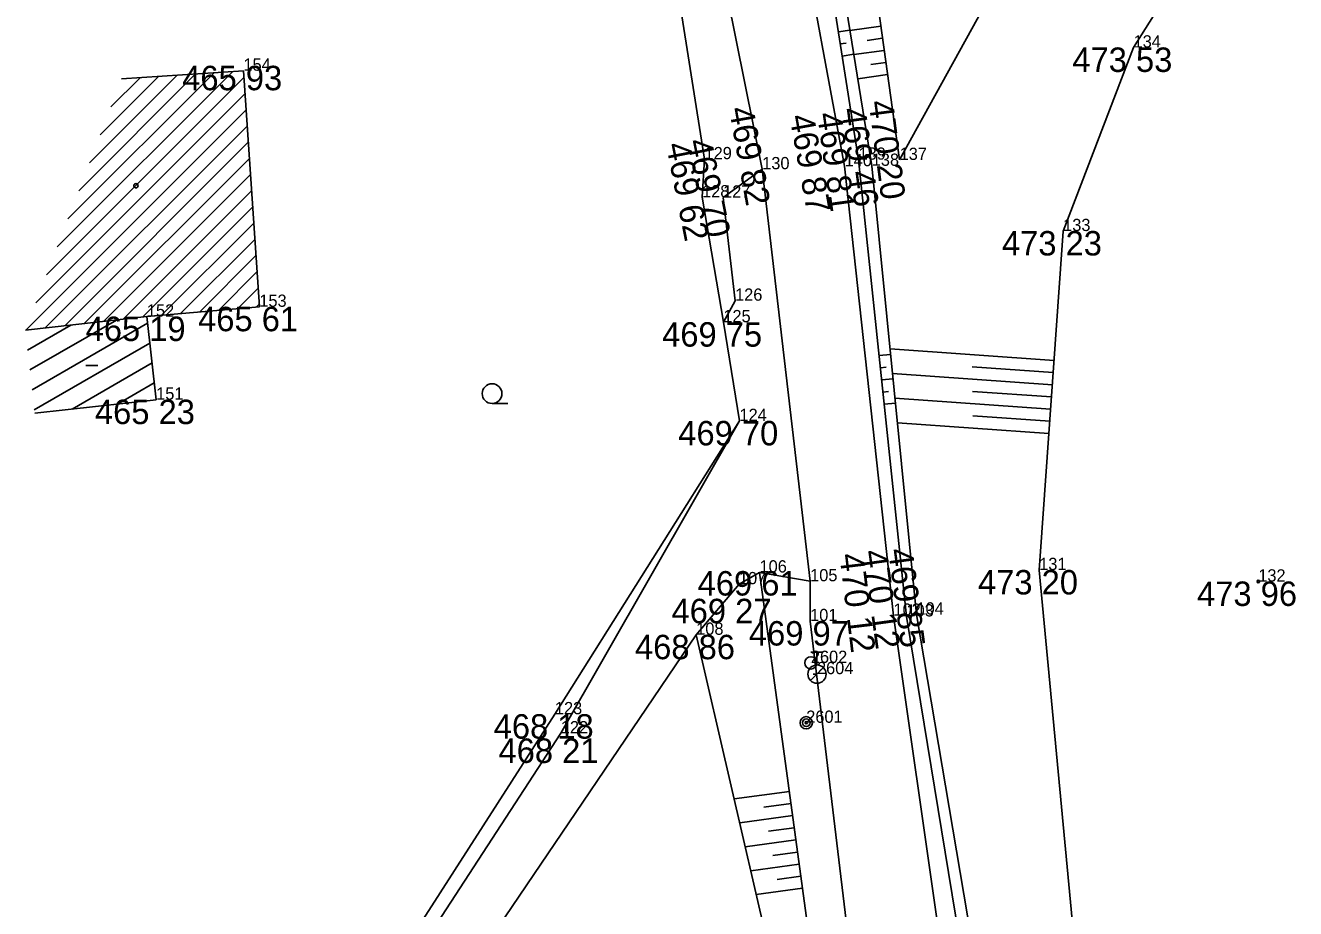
# Model space of a CAD drawing. Extents: x -559180 to -551373, y -1076947 to -1072071.
# Drawn here: x -553603.4 to -553551.5, y -1075411.6 to -1075375.5 of the extents above; entities that cross this region are included whole.
import ezdxf

# ---------------------------------------------------------------- set-up
doc = ezdxf.new("R2010")
doc.units = 0
for name, color, linetype in [('12_PLOTY', 7, 'Continuous'), ('14_BUDOVY', 7, 'Continuous'), ('17_KOMUNIKACE', 7, 'Continuous'), ('1_VODA_ZN', 7, 'Continuous'), ('26_SRAFY', 7, 'Continuous'), ('27_HRANA_PATA', 7, 'Continuous'), ('2_VODOVOD', 7, 'Continuous'), ('32', 7, 'Continuous'), ('3_BODY', 7, 'Continuous'), ('45_ZN_KULTURY', 7, 'Continuous'), ('47_ZN_STAV_OBJ$', 7, 'Continuous'), ('6_VYSKY', 7, 'Continuous')]:
    doc.layers.add(name, color=color, linetype=linetype)

# ---------------------------------------------------------------- blocks, each defined once
blk = doc.blocks.new('POINT_DISPLAY')
blk.add_line((0, 0), (0, 0))
blk = doc.blocks.new('T')
at = {"layer": '6_VYSKY'}
blk.add_circle((0, 0), 0.05, dxfattribs=at)
blk = doc.blocks.new('BZ')
at = {"layer": '47_ZN_STAV_OBJ$'}
blk.add_circle((0, 0), 0.0875, dxfattribs=at)
blk = doc.blocks.new('BD')
at = {"layer": '47_ZN_STAV_OBJ$'}
blk.add_line((-0.25, 0), (0.25, 0), dxfattribs=at)
blk = doc.blocks.new('ZAHRAD')
at = {"layer": '45_ZN_KULTURY'}
blk.add_line((0, 0), (0.65, 0.003), dxfattribs=at)
blk.add_circle((0, 0.403), 0.403, dxfattribs=at)
blk = doc.blocks.new('OSV')
at = {"layer": '1_VODA_ZN'}
for radius in [0.25, 0.158, 0.05]:
    blk.add_circle((0, 0), radius, dxfattribs=at)
blk = doc.blocks.new('SV')
at = {"layer": '1_VODA_ZN'}
blk.add_circle((0, 0), 0.25, dxfattribs=at)
blk = doc.blocks.new('HYP')
at = {"layer": '1_VODA_ZN'}
for p, q in [((-0.25, 0.9), (0.25, 0.9)), ((0, 0.375), (0, 0.9)), ((-0.265, -0.265), (0.265, 0.265))]:
    blk.add_line(p, q, dxfattribs=at)
blk.add_circle((0, 0), 0.375, dxfattribs=at)

msp = doc.modelspace()

# ---------------------------------------------------------------- linework, layer by layer
at = {"layer": '12_PLOTY'}
for p, q in [((-553578.07, -1075365.69), (-553575.67, -1075380.93)), ((-553575.67, -1075380.93), (-553575.77, -1075382.49)), ((-553575.77, -1075382.49), (-553574.9, -1075387.6)), ((-553574.24, -1075391.64), (-553574.9, -1075387.6)), ((-553574.24, -1075391.64), (-553581.79, -1075403.64)), ((-553581.79, -1075403.64), (-553589.76, -1075416.05))]:
    msp.add_line(p, q, dxfattribs=at)
at = {"layer": '14_BUDOVY'}
for p, q in [((-553599.519, -1075377.646), (-553594.53, -1075377.31)), ((-553593.88, -1075386.97), (-553594.53, -1075377.31)), ((-553598.48, -1075387.37), (-553593.88, -1075386.97)), ((-553603.449, -1075387.925), (-553598.48, -1075387.37)), ((-553598.1, -1075390.77), (-553598.48, -1075387.37)), ((-553603.069, -1075391.325), (-553598.1, -1075390.77))]:
    msp.add_line(p, q, dxfattribs=at)
at = {"layer": '17_KOMUNIKACE'}
for p, q in [((-553573.31, -1075381.34), (-553576.49, -1075365.56)), ((-553569.94, -1075381.22), (-553572.85, -1075365.49)), ((-553574.91, -1075382.5), (-553573.31, -1075381.34)), ((-553571.35, -1075398.2), (-553573.31, -1075381.34)), ((-553567.94, -1075399.61), (-553569.94, -1075381.22)), ((-553574.42, -1075386.72), (-553574.91, -1075382.5)), ((-553574.9, -1075387.6), (-553574.42, -1075386.72)), ((-553581.55, -1075404.42), (-553574.24, -1075391.64)), ((-553573.42, -1075397.84), (-553574.26, -1075398.32)), ((-553571.35, -1075398.2), (-553573.42, -1075397.84)), ((-553574.26, -1075398.32), (-553576.01, -1075400.39)), ((-553571.35, -1075399.83), (-553571.35, -1075398.2)), ((-553569.38, -1075416.18), (-553571.35, -1075399.83)), ((-553565.69, -1075415.32), (-553567.94, -1075399.61)), ((-553576.01, -1075400.39), (-553585.06, -1075413.74)), ((-553588.75, -1075415.48), (-553581.55, -1075404.42))]:
    msp.add_line(p, q, dxfattribs=at)
at = {"layer": '26_SRAFY'}
for p, q in [((-553569.725, -1075375.646), (-553570.196, -1075375.72)), ((-553569.721, -1075375.664), (-553568.458, -1075375.487)), ((-553569.882, -1075376.177), (-553570.118, -1075376.214)), ((-553569.015, -1075376.07), (-553568.388, -1075375.982)), ((-553569.566, -1075376.633), (-553570.04, -1075376.708)), ((-553569.562, -1075376.652), (-553568.319, -1075376.477)), ((-553568.866, -1075377.059), (-553568.249, -1075376.972)), ((-553569.403, -1075377.639), (-553568.18, -1075377.467)), ((-553568.061, -1075388.918), (-553568.529, -1075388.967)), ((-553568.084, -1075388.688), (-553561.374, -1075389.162)), ((-553568.244, -1075389.44), (-553568.477, -1075389.464)), ((-553567.983, -1075389.698), (-553561.444, -1075390.16)), ((-553564.721, -1075389.427), (-553561.409, -1075389.661)), ((-553567.961, -1075389.913), (-553568.425, -1075389.962)), ((-553568.142, -1075390.435), (-553568.373, -1075390.459)), ((-553567.883, -1075390.707), (-553561.515, -1075391.157)), ((-553564.706, -1075390.431), (-553561.48, -1075390.659)), ((-553567.862, -1075390.908), (-553568.321, -1075390.956)), ((-553567.782, -1075391.717), (-553561.585, -1075392.155)), ((-553564.691, -1075391.434), (-553561.55, -1075391.656)), ((-553574.459, -1075407.108), (-553572.2, -1075406.801)), ((-553573.239, -1075407.447), (-553572.133, -1075407.296)), ((-553574.233, -1075408.087), (-553572.065, -1075407.791)), ((-553573.059, -1075408.431), (-553571.998, -1075408.287)), ((-553574.007, -1075409.065), (-553571.93, -1075408.782)), ((-553572.879, -1075409.416), (-553571.863, -1075409.278)), ((-553573.782, -1075410.044), (-553571.795, -1075409.773)), ((-553572.698, -1075410.401), (-553571.728, -1075410.269)), ((-553573.556, -1075411.022), (-553571.661, -1075410.764))]:
    msp.add_line(p, q, dxfattribs=at)
at = {"layer": '27_HRANA_PATA'}
for p, q in [((-553568.83, -1075381.2), (-553571.41, -1075365.18)), ((-553559.01, -1075365.18), (-553567.69, -1075380.96)), ((-553569.37, -1075380.95), (-553571.84, -1075365.31)), ((-553558.12, -1075376.36), (-553551.71, -1075366.16)), ((-553567.69, -1075380.96), (-553568.71, -1075373.69)), ((-553561, -1075383.87), (-553558.12, -1075376.36)), ((-553567.41, -1075399.64), (-553569.37, -1075380.95)), ((-553567, -1075399.56), (-553568.83, -1075381.2)), ((-553561.98, -1075397.74), (-553561, -1075383.87)), ((-553570.9, -1075416.35), (-553573.42, -1075397.84)), ((-553560.37, -1075414.83), (-553561.98, -1075397.74)), ((-553564.38, -1075415.07), (-553567, -1075399.56)), ((-553564.87, -1075415.16), (-553567.41, -1075399.64)), ((-553572.42, -1075415.94), (-553576.01, -1075400.39))]:
    msp.add_line(p, q, dxfattribs=at)
at = {"layer": '2_VODOVOD'}
msp.add_line((-553571.22, -1075402), (-553571.07, -1075402), dxfattribs=at)
at = {"layer": '32'}
for p, q in [((-553602.583, -1075385.66), (-553594.511, -1075377.588)), ((-553602.145, -1075384.515), (-553594.97, -1075377.34)), ((-553601.707, -1075383.37), (-553595.728, -1075377.391)), ((-553601.27, -1075382.225), (-553596.486, -1075377.442)), ((-553600.832, -1075381.08), (-553597.244, -1075377.493)), ((-553600.394, -1075379.936), (-553598.003, -1075377.544)), ((-553599.957, -1075378.791), (-553598.761, -1075377.595)), ((-553603.021, -1075386.804), (-553594.467, -1075378.251)), ((-553603.432, -1075387.923), (-553594.422, -1075378.913)), ((-553602.636, -1075387.834), (-553594.378, -1075379.576)), ((-553601.84, -1075387.745), (-553594.333, -1075380.238)), ((-553601.044, -1075387.656), (-553594.288, -1075380.901)), ((-553600.248, -1075387.567), (-553594.244, -1075381.563)), ((-553599.452, -1075387.479), (-553594.199, -1075382.226)), ((-553598.656, -1075387.39), (-553594.155, -1075382.888)), ((-553597.877, -1075387.318), (-553594.11, -1075383.551)), ((-553597.102, -1075387.25), (-553594.065, -1075384.213)), ((-553596.328, -1075387.183), (-553594.021, -1075384.876)), ((-553595.553, -1075387.116), (-553593.976, -1075385.538)), ((-553594.779, -1075387.048), (-553593.932, -1075386.201)), ((-553594.005, -1075386.981), (-553593.887, -1075386.863)), ((-553603.267, -1075389.552), (-553599.729, -1075387.51)), ((-553603.358, -1075388.739), (-553601.589, -1075387.717)), ((-553603.176, -1075390.366), (-553598.45, -1075387.637)), ((-553603.085, -1075391.179), (-553598.359, -1075388.451)), ((-553601.543, -1075391.155), (-553598.268, -1075389.264)), ((-553599.683, -1075390.947), (-553598.177, -1075390.078))]:
    msp.add_line(p, q, dxfattribs=at)

# ---------------------------------------------------------------- block references
at = {"layer": '1_VODA_ZN'}
for name, p in [('POINT_DISPLAY', (-553558.12, -1075376.36)), ('POINT_DISPLAY', (-553594.53, -1075377.31)), ('POINT_DISPLAY', (-553575.67, -1075380.93)), ('POINT_DISPLAY', (-553573.31, -1075381.34)), ('POINT_DISPLAY', (-553569.94, -1075381.22)), ('POINT_DISPLAY', (-553569.37, -1075380.95)), ('POINT_DISPLAY', (-553568.83, -1075381.2)), ('POINT_DISPLAY', (-553567.69, -1075380.96)), ('POINT_DISPLAY', (-553575.77, -1075382.49)), ('POINT_DISPLAY', (-553574.91, -1075382.5)), ('POINT_DISPLAY', (-553561, -1075383.87)), ('POINT_DISPLAY', (-553593.88, -1075386.97)), ('POINT_DISPLAY', (-553574.42, -1075386.72)), ('POINT_DISPLAY', (-553598.48, -1075387.37)), ('POINT_DISPLAY', (-553574.9, -1075387.6)), ('POINT_DISPLAY', (-553598.1, -1075390.77)), ('POINT_DISPLAY', (-553574.24, -1075391.64)), ('POINT_DISPLAY', (-553573.42, -1075397.84)), ('POINT_DISPLAY', (-553561.98, -1075397.74)), ('POINT_DISPLAY', (-553574.26, -1075398.32)), ('POINT_DISPLAY', (-553571.35, -1075398.2)), ('POINT_DISPLAY', (-553553.02, -1075398.21)), ('POINT_DISPLAY', (-553567, -1075399.56)), ('POINT_DISPLAY', (-553571.35, -1075399.83)), ('POINT_DISPLAY', (-553567.94, -1075399.61)), ('POINT_DISPLAY', (-553567.41, -1075399.64)), ('POINT_DISPLAY', (-553576.01, -1075400.39)), ('HYP', (-553571.07, -1075402)), ('SV', (-553571.32, -1075401.54)), ('POINT_DISPLAY', (-553571.32, -1075401.54)), ('POINT_DISPLAY', (-553571.07, -1075402)), ('POINT_DISPLAY', (-553581.79, -1075403.64)), ('OSV', (-553571.51, -1075403.99)), ('POINT_DISPLAY', (-553571.51, -1075403.99)), ('POINT_DISPLAY', (-553581.55, -1075404.42))]:
    msp.add_blockref(name, p, dxfattribs=at)
at = {"layer": '32'}
for p in [(-553599.519, -1075377.646), (-553603.449, -1075387.925)]:
    msp.add_blockref('POINT_DISPLAY', p, dxfattribs=at)
at = {"layer": '45_ZN_KULTURY'}
msp.add_blockref('ZAHRAD', (-553584.362, -1075390.926), dxfattribs=at)
at = {"layer": '47_ZN_STAV_OBJ$'}
for name, p in [('BZ', (-553598.928, -1075382.018)), ('BD', (-553600.731, -1075389.377))]:
    msp.add_blockref(name, p, dxfattribs=at)
at = {"layer": '6_VYSKY'}
msp.add_blockref('T', (-553553.02, -1075398.21), dxfattribs=at)
msp.add_blockref('T', (-553553.02, -1075398.21), dxfattribs=at)

# ---------------------------------------------------------------- texts
at = {"layer": '3_BODY'}
for s, p in [('134', (-553558.12, -1075376.36)), ('154', (-553594.53, -1075377.31)), ('129', (-553575.67, -1075380.93)), ('130', (-553573.31, -1075381.34)), ('140', (-553569.94, -1075381.22)), ('139', (-553569.37, -1075380.95)), ('138', (-553568.83, -1075381.2)), ('137', (-553567.69, -1075380.96)), ('128', (-553575.77, -1075382.49)), ('127', (-553574.91, -1075382.5)), ('133', (-553561, -1075383.87)), ('153', (-553593.88, -1075386.97)), ('126', (-553574.42, -1075386.72)), ('152', (-553598.48, -1075387.37)), ('125', (-553574.9, -1075387.6)), ('151', (-553598.1, -1075390.77)), ('124', (-553574.24, -1075391.64)), ('106', (-553573.42, -1075397.84)), ('131', (-553561.98, -1075397.74)), ('107', (-553574.26, -1075398.32)), ('105', (-553571.35, -1075398.2)), ('132', (-553553.02, -1075398.21)), ('104', (-553567, -1075399.56)), ('101', (-553571.35, -1075399.83)), ('102', (-553567.94, -1075399.61)), ('103', (-553567.41, -1075399.64)), ('108', (-553576.01, -1075400.39)), ('2602', (-553571.32, -1075401.54)), ('2604', (-553571.07, -1075402)), ('123', (-553581.79, -1075403.64)), ('2601', (-553571.51, -1075403.99)), ('122', (-553581.55, -1075404.42))]:
    msp.add_text(s, height=0.5, dxfattribs=at).set_placement(p)
at = {"layer": '6_VYSKY'}
for s, p in [('473 53', (-553560.625, -1075377.36)), ('465 93', (-553597.035, -1075378.109)), ('473 23', (-553563.505, -1075384.87)), ('465 61', (-553596.385, -1075387.97)), ('465 19', (-553600.985, -1075388.37)), ('469 75', (-553577.405, -1075388.6)), ('465 23', (-553600.605, -1075391.77)), ('469 70', (-553576.745, -1075392.64)), ('469 61', (-553575.953, -1075398.784)), ('473 20', (-553564.485, -1075398.74)), ('473 96', (-553555.525, -1075399.21)), ('469 27', (-553577.021, -1075399.917)), ('469 97', (-553573.855, -1075400.83)), ('468 86', (-553578.515, -1075401.39)), ('468 18', (-553584.295, -1075404.64)), ('468 21', (-553584.097, -1075405.633))]:
    msp.add_text(s, height=1, dxfattribs=at).set_placement(p)
for s, rotation, p in [('470 20', 277.3757, (-553568.96, -1075378.577)), ('469 82', 280.0645, (-553574.672, -1075378.864)), ('469 87', 280.2722, (-553572.2, -1075379.178)), ('469 81', 277.9685, (-553571.068, -1075379.073)), ('469 46', 277.8273, (-553570.083, -1075378.881)), ('469 62', 281.1178, (-553577.249, -1075380.333)), ('469 70', 281.4005, (-553576.378, -1075380.192)), ('470 12', 277.8002, (-553569.203, -1075396.973)), ('469 85', 277.5876, (-553568.163, -1075396.911)), ('470 12', 276.8637, (-553570.156, -1075397.109))]:
    msp.add_text(s, height=1, rotation=rotation, dxfattribs=at).set_placement(p)

doc.saveas('drawing.dxf')
